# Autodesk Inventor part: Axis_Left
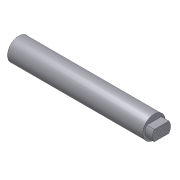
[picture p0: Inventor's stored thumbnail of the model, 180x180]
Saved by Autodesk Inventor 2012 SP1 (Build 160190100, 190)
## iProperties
Created: 2006-03
Part Number: Axis_Left
Document SubType Name: Modeling
Material: Stainless Steel, 440C
Mass: 126.376 g
Surface Area: 47.6763 cm^2
Volume: 16.3066 cm^3
Density: 7.75 g/cm^3
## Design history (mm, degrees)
sketch "Sketch1"
  geometry: L1 (-4.823, 3.575)-(4.823, 3.575); L2 (4.823, 3.575)-(4.823, -3.575); L3 (4.823, -3.575)-(-4.822, -3.575); L4 (-4.822, -3.575)-(-4.823, 3.575); L5 (-4.823, 3.575)-(4.823, -3.575); L6 (-7.205, 0)-(9.606, 0) reference; A1 r 6 centre (-0.004, 0) between (-4.823, 3.575) and (-4.822, -3.575); A2 r 6 centre (0.004, 0) between (4.823, -3.575) and (4.823, 3.575); 2 further points
  constraints: 10 end point, 4 point on circle, 2 centre point, 2 parallel, 2 point on line, 1 coincident, 1 equal radius, 1 horizontal, 1 midpoint, 1 perpendicular
  dimensions: "d0" = 9.645 distance of L2.end L3.end; "d1" = 7.15 distance of L3.end L1.start; "d2" = 6 radius of A1
extrude "Extrusion1" new body sketch "Sketch1" distance "d3" = 5; taper "d4" = 0 deg
sketch "Sketch2"
  geometry: C1 r 7.5 at (0, 0); 1 further point
  constraints: 1 centre point, 1 coincident
  dimensions: "d5" = 15 diameter of C1
extrude "Extrusion2" join sketch "Sketch2" distance "d6" = 90; taper "d7" = 0 deg
body "Solid1"
